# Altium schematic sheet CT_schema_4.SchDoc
size 357 x 184 mm
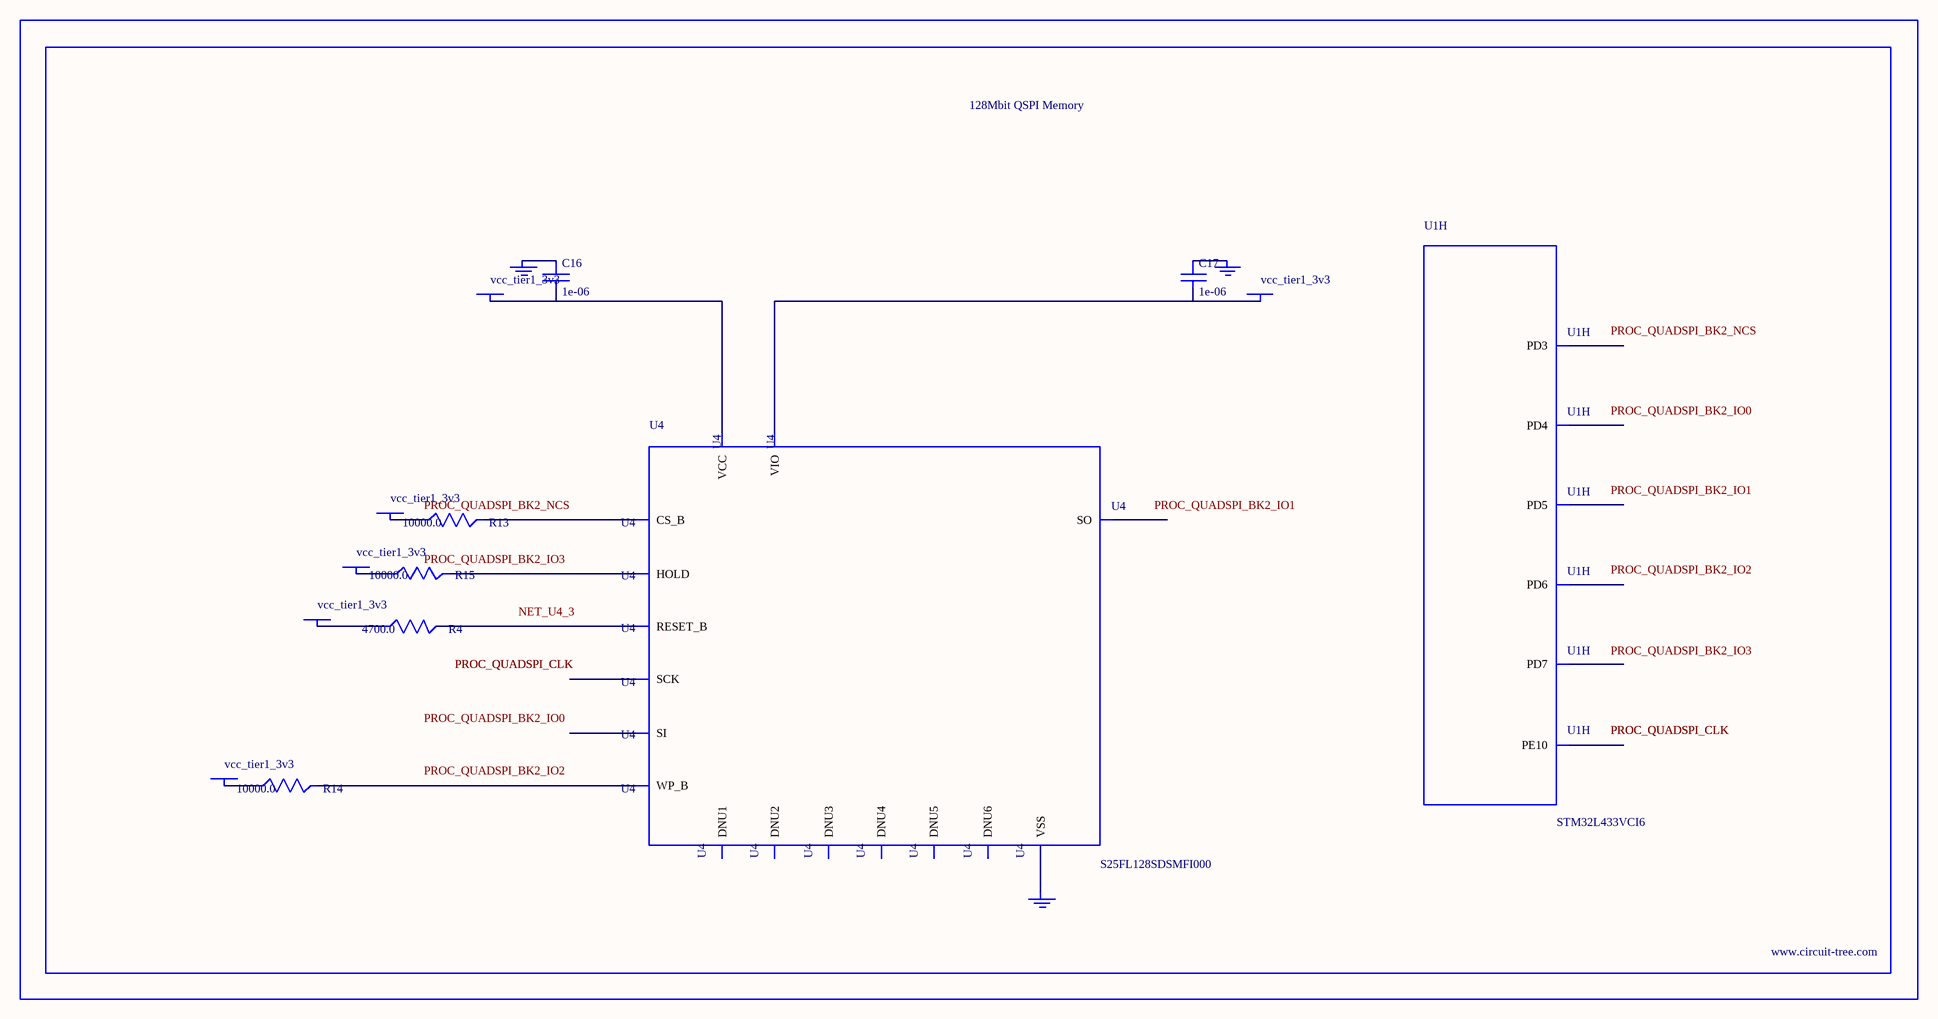
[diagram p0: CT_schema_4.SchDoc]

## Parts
BORDER3  (no value)
C16  1e-06  [C0603]
C17  1e-06  [C0603]
GND_INSTANCE_3_0  (no value)
GND_INSTANCE_3_1  (no value)
GND_INSTANCE_3_2  (no value)
POWER_INSTANCE_3_0  vcc_tier1_3v3
POWER_INSTANCE_3_1  vcc_tier1_3v3
POWER_INSTANCE_3_2  vcc_tier1_3v3
POWER_INSTANCE_3_3  vcc_tier1_3v3
POWER_INSTANCE_3_4  vcc_tier1_3v3
POWER_INSTANCE_3_5  vcc_tier1_3v3
R4  4700.0  [R0603]
R13  10000.0  [R0603]
R14  10000.0  [R0603]
R15  10000.0  [R0603]
U1  STM32L433VCI6  [UFBGA100]  (part H of 11)
U4  S25FL128SDSMFI000  [S25FL128SDSMFI000]

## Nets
NetC16_1: C16.1 GND_INSTANCE_3_0.0(GND)
NetC16_2: C16.2 POWER_INSTANCE_3_1.0(PWR) U4.2(VCC)
NetC17_1: C17.1 GND_INSTANCE_3_1.0(GND)
NetC17_2: C17.2 POWER_INSTANCE_3_4.0(PWR) U4.14(VIO)
NetGND_INSTANCE_3_2_0: GND_INSTANCE_3_2.0(GND) U4.10(VSS)
NetPOWER_INSTANCE_3_0_0: POWER_INSTANCE_3_0.0(PWR) R15.1
NetPOWER_INSTANCE_3_2_0: POWER_INSTANCE_3_2.0(PWR) R13.1
NetPOWER_INSTANCE_3_3_0: POWER_INSTANCE_3_3.0(PWR) R14.1
NetPOWER_INSTANCE_3_5_0: POWER_INSTANCE_3_5.0(PWR) R4.1
NetR4_2: R4.2 U4.3(RESET_B)
NetR13_2: R13.2 U4.7(CS_B)
NetR14_2: R14.2 U4.9(WP_B)
NetR15_2: R15.2 U4.1(HOLD)

Not connected (* = marked no-connect by the designer): U1 A5(PD7) A6(PD5) B6(PD6) B7(PD4) B8(PD3) L8(PE10); U4 4(DNU1) 5(DNU2) 6(DNU6) 8(SO) 11(DNU3) 12(DNU4) 13(DNU5) 15(SI) 16(SCK)

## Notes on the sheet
- Labels drawn without touching a wire or pin: NET_U4_3, PROC_QUADSPI_BK2_IO0, PROC_QUADSPI_BK2_IO1, PROC_QUADSPI_BK2_IO2, PROC_QUADSPI_BK2_IO3, PROC_QUADSPI_BK2_NCS

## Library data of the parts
BORDER3 = BORDER_PAGE3
C16 C17 = C0603C105K3RACTU
GND_INSTANCE_3_0-GND_INSTANCE_3_2 = GND
POWER_INSTANCE_3_0-POWER_INSTANCE_3_5 = PWR
R4 = RC0603JR-074K7L
R13-R15 = RC0603JR-0710KL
